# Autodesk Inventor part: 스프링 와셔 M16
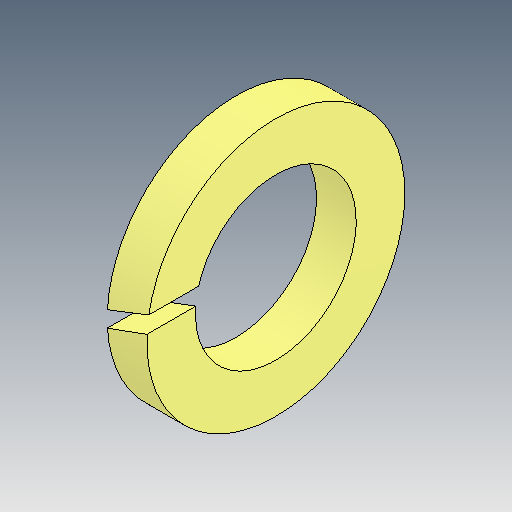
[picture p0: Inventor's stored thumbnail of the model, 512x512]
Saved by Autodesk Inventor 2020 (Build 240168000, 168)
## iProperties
Created: 2025-01
Part Number: 스프링 와셔 M16
Material: 강철, 연강
Description: 스프링 잠금 와셔
Document SubType Name: Modeling
Designer: 1강의실14
Density: 7.85 g/cm^3
Appearance: 기본값
Author: jhkim
Sending System: Autodesk Inventor 2025
Preprocessor: ST-DEVELOPER v20
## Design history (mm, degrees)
feature "Solid1"
node "솔리드1"
